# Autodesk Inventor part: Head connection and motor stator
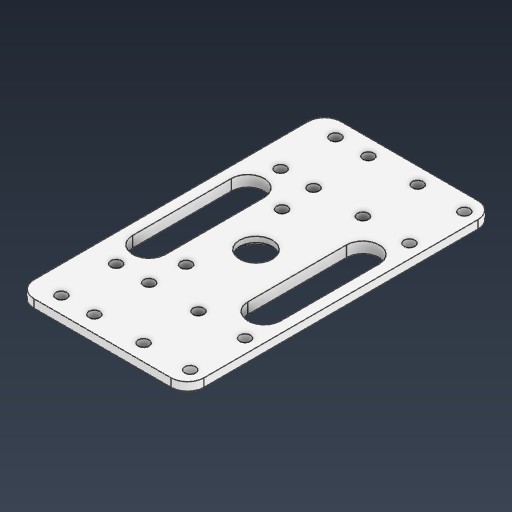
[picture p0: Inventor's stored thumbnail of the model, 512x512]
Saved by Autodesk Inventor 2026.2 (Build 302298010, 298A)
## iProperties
Created: 2026-05
Part Number: Head connection and motor stator
Material: PLA
Document SubType Name: Modeling
Designer: work
Density: 1.24 g/cm^3
Appearance: 일반
Mass: 26.8868 g
Surface Area: 140.131 cm^2
Volume: 21.6829 cm^3
Author: work
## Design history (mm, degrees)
sketch "스케치1"
  geometry: L1 (-9, 10)-(-26, 10); L2 (-26, 10)-(-26, -10); L3 (-26, -10)-(-9, -10); L4 (-9, -10)-(-9, 10); L5 (-9, 0)-(9, 0); L6 (21, 10)-(9, 10); L7 (9, 10)-(9, -10); L8 (9, -10)-(21, -10); L9 (21, -10)-(21, 10); L10 (-9, -90)-(-9, -70); L11 (-9, -70)-(-26, -70); L12 (-26, -70)-(-26, -90); L13 (-26, -90)-(-9, -90); L14 (-9, -80)-(9, -80); L15 (9, -70)-(9, -90); L16 (9, -90)-(21, -90); L17 (21, -70)-(9, -70); L18 (21, -90)-(21, -70); L19 (0, 0)-(0, -80); L20 (0, -40)-(8, -40); L21 (8, -22.5)-(8, -57.5); L22 (8, -22.5)-(43, -22.5); L23 (-31, 16)-(31, 16); L24 (31, 16)-(31, -96); L25 (31, -96)-(-31, -96); L26 (-31, -96)-(-31, 16); L27 (-31, 16)-(31, -96); L28 (31, 16)-(-31, -96); L29 (-27, -16)-(-15, -16); L30 (-15, -16)-(-15, -64); L31 (-15, -64)-(-27, -64); L32 (-27, -64)-(-27, -16); L33 (-27, -16)-(-15, -64); L34 (-15, -16)-(-27, -64); L35 (-31, -40)-(31, -40); L36 (31, -40)-(-31, -40); L37 (15, -16)-(15, -64); L38 (27, -64)-(27, -16); L39 (27, -16)-(15, -64); L40 (15, -16)-(27, -64); L41 (31, 16)-(-31, -96); L42 (-31, 16)-(31, -96); L43 (27, -16)-(15, -16); L44 (15, -64)-(27, -64); C1 r 2 at (21, 10); C2 r 2 at (9, 10); C3 r 2 at (9, -10); C4 r 2 at (21, -10); C5 r 2 at (-9, 10); C6 r 2 at (-9, -10); C7 r 2 at (-26, -10); C8 r 2 at (-26, 10); C9 r 2 at (-9, -70); C10 r 2 at (-9, -90); C11 r 2 at (-26, -70); C12 r 2 at (-26, -90); C13 r 2 at (9, -90); C14 r 2 at (9, -70); C15 r 2 at (21, -90); C16 r 2 at (21, -70); C17 r 6 at (0, -40); C18 r 2 at (8, -22.5); C19 r 2 at (8, -57.5); 13 further points
  constraints: 88 end point, 20 coincident, 19 centre point, 15 midpoint, 12 parallel, 11 symmetric about line, 10 horizontal, 8 perpendicular, 2 point on line, 1 vertical
  dimensions: "d0" = 20 distance of L3.end L1.start; "d1" = 18 distance of L5.end L5.start; "d2" = 17 distance of L2.end L3.end; "d3" = 12 distance of L8.end L7.end; "d4" = 20 distance of L7.end L6.end; "d5" = 4 diameter of C1; "d6" = 4 diameter of C2; "d7" = 4 diameter of C3; "d8" = 4 diameter of C4; "d9" = 4 diameter of C5; "d10" = 4 diameter of C6; "d11" = 4 diameter of C7; "d12" = 4 diameter of C8; "d13" = 20 distance of L10.start L10.end; "d14" = 18 distance of L14.end L14.start; "d15" = 17 distance of L12.end L10.start; "d16" = 12 distance of L16.end L15.end; "d17" = 20 distance of L15.end L15.start; "d18" = 4 diameter of C16; "d19" = 4 diameter of C14; "d20" = 4 diameter of C13; "d21" = 4 diameter of C15; "d22" = 4 diameter of C9; "d23" = 4 diameter of C10; "d24" = 4 diameter of C12; "d25" = 4 diameter of C11; "d26" = 80 distance of L19.start L19.end; "d27" = 12 diameter of C17; "d28" = 8 distance of L20.start L20.end; "d29" = 35 distance of L21.start L21.end; "d30" = 90 deg angle of L21 L22 (derived); "d31" = 4 diameter of C18; "d32" = 4 diameter of C19; "d33" = 10 distance between parallel lines of L24 L9; "d34" = 6 distance between parallel lines of L23 L6; "d35" = 6 distance from line of point (-17.5, -70) L31; "d36" = 4 distance between parallel lines of L26 L32; "d37" = 10 distance of L35.start point (-21, -40)
extrude "돌출1" new body sketch "스케치1" distance "d38" = 4; taper "d39" = 0 deg
fillet "모깎기1" dims "d40" = 6
chamfer "모따기1" distance "d41" = 2; stored, may be unused: second distance "d42" = 2, angle "d43" = 45 deg
chamfer "모따기2" distance "d44" = 1; stored, may be unused: second distance "d45" = 2, angle "d46" = 45 deg
feature "Ǌ耀ǌ耀ǎ耀ǐ耀ǒ耀ǔ耀ǖ耀ǘ耀" dims "d0" = 20, "d1" = 18, "d2" = 17, "d3" = 12, "d4" = 20, "d5" = 4, "d6" = 4, "d7" = 4, "d8" = 4, "d9" = 4, "d10" = 4, "d11" = 4, "d12" = 4, "d13" = 20, "d14" = 18, "d15" = 17, "d16" = 12, "d17" = 20, "d18" = 4, "d19" = 4, "d20" = 4, "d21" = 4, "d22" = 4, "d23" = 4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
node "솔리드1"
